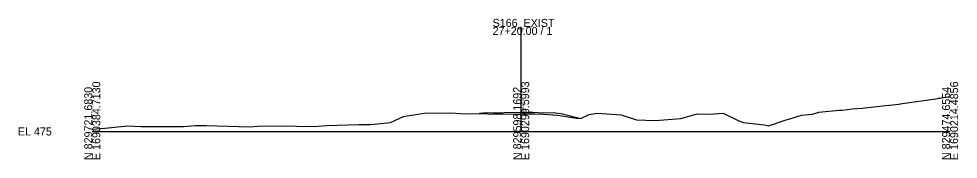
# Model space of a CAD drawing. Extents: x 1621104 to 1621433, y 1192880 to 1199414.
# Drawn here: x 1621104.2 to 1621432.7, y 1192879.5 to 1192928.6 of the extents above; entities that cross this region are included whole.
import ezdxf

# ---------------------------------------------------------------- set-up
doc = ezdxf.new("R2010")
doc.units = 0
for name, color, linetype in [('RD_GPK_XS_Cell', 7, 'Continuous'), ('RD_XS_EarthShd', 7, 'Continuous'), ('RD_XS_ExGround', 7, 'Continuous'), ('RD_XS_Pave', 7, 'Continuous'), ('RD_XS_TieSlope', 7, 'Continuous'), ('RD_XS_TX_Elev_EX', 7, 'Continuous'), ('RD_XS_TX_Elev_PR', 7, 'Continuous')]:
    doc.layers.add(name, color=color, linetype=linetype)

msp = doc.modelspace()

# ---------------------------------------------------------------- linework, layer by layer
at = {"layer": 'RD_GPK_XS_Cell'}
for p, q in [((1621279.86, 1192889.24), (1621279.86, 1192925.79)), ((1621129.86, 1192889.24), (1621279.86, 1192889.24)), ((1621279.86, 1192889.24), (1621429.86, 1192889.24))]:
    msp.add_line(p, q, dxfattribs=at)
at = {"layer": 'RD_XS_EarthShd'}
for p, q in [((1621267.86, 1192895.7), (1621265.29, 1192895.49)), ((1621291.86, 1192895.7), (1621293.86, 1192895.54))]:
    msp.add_line(p, q, dxfattribs=at)
at = {"layer": 'RD_XS_ExGround'}
msp.add_lwpolyline([(1621129.86, 1192890.1), (1621134.23, 1192890.44), (1621142.26, 1192891.19), (1621146.83, 1192890.93), (1621161.73, 1192890.99), (1621164.56, 1192891.2), (1621165.98, 1192891.32), (1621167.76, 1192891.31), (1621169.7, 1192891.3), (1621184.93, 1192890.81), (1621187.64, 1192891.08), (1621198.06, 1192891.16), (1621201.31, 1192891.1), (1621204.87, 1192890.97), (1621208.73, 1192891.04), (1621211.94, 1192891.33), (1621219.28, 1192891.56), (1621223.11, 1192891.64), (1621227.21, 1192891.68), (1621234.18, 1192892.39), (1621238.69, 1192894.45), (1621239.99, 1192894.76), (1621246.03, 1192895.63), (1621255.13, 1192895.7), (1621260.31, 1192895.43), (1621267.19, 1192895.52), (1621269.15, 1192895.28), (1621270.35, 1192895.35), (1621273.5, 1192895.35), (1621277.52, 1192895.3), (1621279.86, 1192895.33), (1621281.16, 1192895.35), (1621284.59, 1192895.4), (1621287.68, 1192895.34), (1621292.6, 1192894.95), (1621295.64, 1192894.45), (1621299.15, 1192893.93), (1621300.68, 1192893.81), (1621303.69, 1192895.21), (1621306.44, 1192895.61), (1621314.78, 1192895.07), (1621320.14, 1192893.29), (1621326.74, 1192893.08), (1621335.71, 1192893.82), (1621339.39, 1192894.77), (1621341.35, 1192895.36), (1621345.78, 1192895.34), (1621350.5, 1192895.67), (1621355.99, 1192893.01), (1621357.58, 1192892.39), (1621364.9, 1192891.59), (1621366.4, 1192891.19), (1621372.57, 1192893.28), (1621373.47, 1192893.49), (1621377.92, 1192894.91), (1621381.75, 1192895.24), (1621383.9, 1192895.99), (1621391.03, 1192896.64), (1621391.76, 1192896.71), (1621392.16, 1192896.74), (1621395.56, 1192897.13), (1621399.06, 1192897.38), (1621400.07, 1192897.48), (1621407.35, 1192898.28), (1621412, 1192898.81), (1621412.45, 1192898.86), (1621425.52, 1192900.8), (1621425.9, 1192900.86), (1621426.28, 1192900.88), (1621426.69, 1192900.97), (1621429.86, 1192901.42)], dxfattribs=at)
at = {"layer": 'RD_XS_Pave'}
for p, q in [((1621267.86, 1192895.7), (1621279.86, 1192895.94)), ((1621279.86, 1192895.94), (1621291.86, 1192895.7))]:
    msp.add_line(p, q, dxfattribs=at)
at = {"layer": 'RD_XS_TieSlope'}
msp.add_line((1621293.86, 1192895.54), (1621300.72, 1192893.82), dxfattribs=at)

# ---------------------------------------------------------------- texts
at = {"layer": 'RD_GPK_XS_Cell'}
for s, p in [('S166_EXIST', (1621269.86, 1192925.79)), ('27+20.00 / 1', (1621269.86, 1192922.99)), ('EL 475', (1621103.86, 1192887.84))]:
    msp.add_text(s, height=2.8, dxfattribs=at).set_placement(p)
for s, p in [('E 1690384.7130', (1621132.66, 1192879.24)), ('E 1690299.5993', (1621282.66, 1192879.24)), ('E 1690214.4856', (1621432.66, 1192879.24)), ('N 829721.6830', (1621129.86, 1192879.24)), ('N 829598.1692', (1621279.86, 1192879.24)), ('N 829474.6554', (1621429.86, 1192879.24))]:
    msp.add_text(s, height=2.8, rotation=90, dxfattribs=at).set_placement(p)
at = {"layer": 'RD_XS_TX_Elev_EX'}
msp.add_text('481.09', height=1, dxfattribs=at).set_placement((1621279.76, 1192895.43))
at = {"layer": 'RD_XS_TX_Elev_PR'}
msp.add_text(' 481.70', height=1, rotation=90, dxfattribs=at).set_placement((1621280.86, 1192895.94))

doc.saveas('drawing.dxf')
